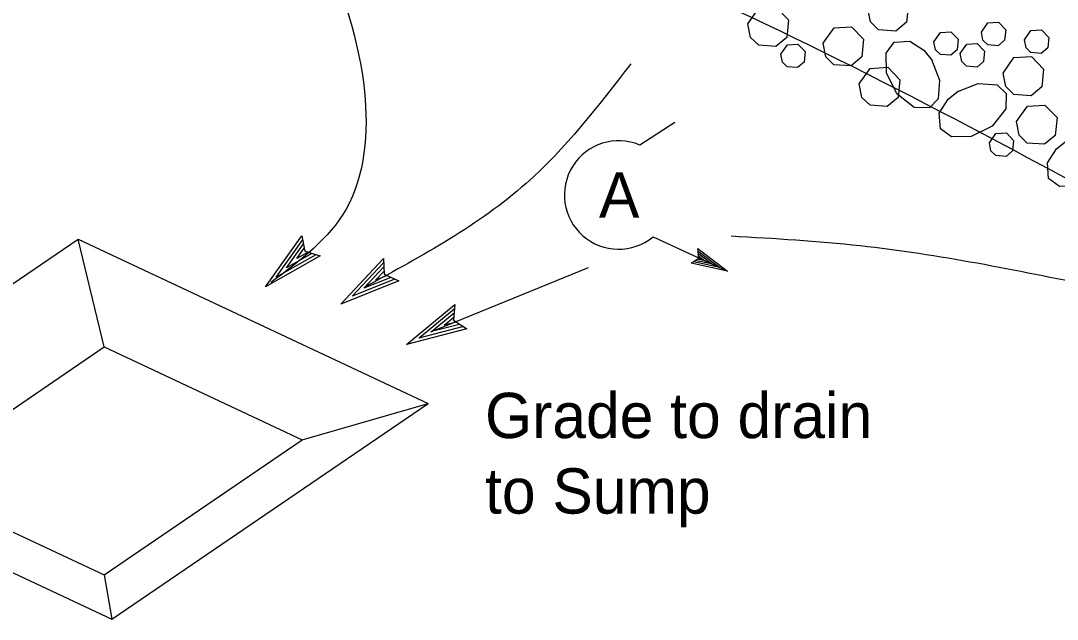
# Model space of a CAD drawing. Extents: x 6707406 to 6714471, y 1868570 to 1872341.
# Drawn here: x 6710587.1 to 6710751.9, y 1870221.6 to 1870316.7 of the extents above; entities that cross this region are included whole.
import ezdxf

# ---------------------------------------------------------------- set-up
doc = ezdxf.new("R2010")
doc.units = 0
for name, color, linetype in [('56 Stg 3 Anno', 7, 'Continuous'), ('57 Undefined', 7, 'Continuous'), ('60 Nongeo Data', 7, 'Continuous')]:
    doc.layers.add(name, color=color, linetype=linetype)

msp = doc.modelspace()

# ---------------------------------------------------------------- linework, layer by layer
at = {"layer": '56 Stg 3 Anno'}
for p, q in [((6710691.06, 1870300.55), (6710685.5, 1870296.97)), ((6710687.63, 1870282.38), (6710699.46, 1870276.93)), ((6710694.92, 1870279.02), (6710694.76, 1870280.51)), ((6710694.76, 1870280.51), (6710694.76, 1870280.51)), ((6710694.76, 1870280.51), (6710699.46, 1870276.93)), ((6710693.69, 1870278.18), (6710694.92, 1870279.02)), ((6710695.84, 1870278.6), (6710694.68, 1870278.85)), ((6710694.81, 1870280.11), (6710698.26, 1870277.49)), ((6710694.87, 1870279.71), (6710697.05, 1870278.04)), ((6710694.88, 1870279.33), (6710695.84, 1870278.6)), ((6710699.46, 1870276.93), (6710693.69, 1870278.18)), ((6710693.69, 1870278.18), (6710693.69, 1870278.18)), ((6710698.24, 1870277.49), (6710694.04, 1870278.4)), ((6710697.05, 1870278.04), (6710694.33, 1870278.63)), ((6710699.46, 1870276.93), (6710699.46, 1870276.93))]:
    msp.add_line(p, q, dxfattribs=at)
msp.add_arc((6710682.15, 1870289.04), 8.62, 67.1261, 309.4327, dxfattribs=at)
at = {"layer": '60 Nongeo Data'}
for p, q in [((6710545.91, 1870247.74), (6710596.21, 1870282.03)), ((6710596.21, 1870282.03), (6710651.87, 1870255.89)), ((6710600.37, 1870264.89), (6710596.21, 1870282.03)), ((6710626.02, 1870274.46), (6710631.78, 1870282.56)), ((6710631.78, 1870282.56), (6710631.78, 1870282.56)), ((6710631.78, 1870282.56), (6710632.26, 1870280.1)), ((6710627.69, 1870275.98), (6710631.89, 1870281.88)), ((6710629.34, 1870277.46), (6710632.05, 1870281.27)), ((6710631, 1870278.95), (6710632.16, 1870280.58)), ((6710634.68, 1870279.36), (6710626.02, 1870274.46)), ((6710634.03, 1870279.55), (6710627.68, 1870275.96)), ((6710633.36, 1870279.73), (6710629.34, 1870277.46)), ((6710632.77, 1870279.95), (6710631, 1870278.95)), ((6710632.26, 1870280.1), (6710634.68, 1870279.36)), ((6710634.68, 1870279.36), (6710634.68, 1870279.36)), ((6710637.96, 1870271.69), (6710644.74, 1870278.96)), ((6710644.74, 1870278.96), (6710644.74, 1870278.96)), ((6710644.74, 1870278.96), (6710644.89, 1870276.45)), ((6710639.81, 1870272.97), (6710644.76, 1870278.26)), ((6710641.64, 1870274.22), (6710644.84, 1870277.64)), ((6710677.28, 1870277.46), (6710652.25, 1870267.22)), ((6710647.18, 1870275.4), (6710637.96, 1870271.69)), ((6710646.57, 1870275.67), (6710639.8, 1870272.96)), ((6710645.93, 1870275.94), (6710641.64, 1870274.22)), ((6710643.49, 1870275.48), (6710644.85, 1870276.95)), ((6710645.38, 1870276.24), (6710643.49, 1870275.48)), ((6710644.89, 1870276.45), (6710647.18, 1870275.4)), ((6710647.18, 1870275.4), (6710647.18, 1870275.4)), ((6710626.02, 1870274.46), (6710626.02, 1870274.46)), ((6710637.96, 1870271.69), (6710637.96, 1870271.69)), ((6710648.41, 1870265.3), (6710656.08, 1870271.62)), ((6710650.42, 1870266.32), (6710656.01, 1870270.93)), ((6710656.08, 1870271.62), (6710655.91, 1870269.12)), ((6710656.08, 1870271.62), (6710656.08, 1870271.62)), ((6710652.4, 1870267.32), (6710656.01, 1870270.3)), ((6710654.39, 1870268.34), (6710655.93, 1870269.61)), ((6710656.36, 1870268.84), (6710654.39, 1870268.34)), ((6710655.91, 1870269.12), (6710658.04, 1870267.77)), ((6710658.04, 1870267.77), (6710648.41, 1870265.3)), ((6710657.47, 1870268.13), (6710650.4, 1870266.31)), ((6710656.87, 1870268.47), (6710652.4, 1870267.32)), ((6710658.04, 1870267.77), (6710658.04, 1870267.77)), ((6710568.89, 1870243.43), (6710600.37, 1870264.89)), ((6710600.37, 1870264.89), (6710631.82, 1870250.12)), ((6710648.41, 1870265.3), (6710648.41, 1870265.3)), ((6710601.56, 1870221.61), (6710651.87, 1870255.89)), ((6710631.82, 1870250.12), (6710651.87, 1870255.89)), ((6710600.34, 1870228.66), (6710631.82, 1870250.12)), ((6710545.91, 1870247.74), (6710601.56, 1870221.61)), ((6710568.89, 1870243.43), (6710600.34, 1870228.66)), ((6710600.34, 1870228.66), (6710601.56, 1870221.61))]:
    msp.add_line(p, q, dxfattribs=at)
for points in [[(6710721.77, 1870318.7), (6710723.51, 1870321.18), (6710726.28, 1870321.33), (6710728.21, 1870319.33), (6710727.93, 1870316.53), (6710726.22, 1870315.1), (6710723.48, 1870315.3), (6710722.19, 1870316.55), (6710721.77, 1870318.7)], [(6710702.69, 1870316.24), (6710704.43, 1870318.71), (6710707.21, 1870318.87), (6710709.14, 1870316.87), (6710708.86, 1870314.06), (6710707.15, 1870312.64), (6710704.41, 1870312.84), (6710703.11, 1870314.09), (6710702.7, 1870316.24)], [(6710714.65, 1870313.15), (6710716.39, 1870315.63), (6710719.16, 1870315.78), (6710721.09, 1870313.78), (6710720.82, 1870310.98), (6710719.1, 1870309.55), (6710716.36, 1870309.75), (6710715.07, 1870311), (6710714.65, 1870313.15)], [(6710732.27, 1870313.4), (6710733.31, 1870314.88), (6710734.98, 1870314.98), (6710736.14, 1870313.78), (6710735.97, 1870312.1), (6710734.94, 1870311.24), (6710733.3, 1870311.36), (6710732.52, 1870312.11), (6710732.27, 1870313.4)], [(6710739.81, 1870314.93), (6710740.85, 1870316.42), (6710742.52, 1870316.51), (6710743.68, 1870315.31), (6710743.51, 1870313.63), (6710742.48, 1870312.77), (6710740.83, 1870312.89), (6710740.06, 1870313.64), (6710739.81, 1870314.93)], [(6710746.66, 1870313.71), (6710747.7, 1870315.19), (6710749.37, 1870315.29), (6710750.53, 1870314.09), (6710750.36, 1870312.41), (6710749.33, 1870311.55), (6710747.69, 1870311.67), (6710746.91, 1870312.42), (6710746.66, 1870313.71)], [(6710731.89, 1870310.57), (6710733.18, 1870307.31), (6710732.92, 1870304.32), (6710731.57, 1870302.9), (6710729.15, 1870302.95), (6710726.39, 1870305.1), (6710724.73, 1870308.44), (6710724.67, 1870311.58), (6710725.93, 1870313.35), (6710728.43, 1870313.51), (6710730.66, 1870312.08), (6710731.98, 1870310.44)], [(6710707.92, 1870311.44), (6710708.97, 1870312.92), (6710710.63, 1870313.02), (6710711.79, 1870311.82), (6710711.63, 1870310.13), (6710710.6, 1870309.28), (6710708.95, 1870309.4), (6710708.18, 1870310.15), (6710707.93, 1870311.44)], [(6710736.45, 1870311.54), (6710737.49, 1870313.03), (6710739.16, 1870313.12), (6710740.32, 1870311.92), (6710740.15, 1870310.24), (6710739.12, 1870309.38), (6710737.47, 1870309.5), (6710736.7, 1870310.25), (6710736.45, 1870311.54)], [(6710743.26, 1870308.41), (6710745, 1870310.88), (6710747.78, 1870311.04), (6710749.71, 1870309.04), (6710749.43, 1870306.23), (6710747.71, 1870304.81), (6710744.97, 1870305.01), (6710743.68, 1870306.26), (6710743.26, 1870308.41)], [(6710720.4, 1870306.7), (6710722.14, 1870309.17), (6710724.92, 1870309.33), (6710726.85, 1870307.33), (6710726.57, 1870304.53), (6710724.85, 1870303.1), (6710722.11, 1870303.3), (6710720.82, 1870304.55), (6710720.4, 1870306.7)], [(6710736.07, 1870305.49), (6710739.32, 1870306.78), (6710742.31, 1870306.53), (6710743.73, 1870305.18), (6710743.69, 1870302.75), (6710741.53, 1870299.99), (6710738.2, 1870298.33), (6710735.06, 1870298.27), (6710733.29, 1870299.53), (6710733.13, 1870302.03), (6710734.56, 1870304.27), (6710736.2, 1870305.58)], [(6710745.4, 1870300.7), (6710747.14, 1870303.17), (6710749.92, 1870303.33), (6710751.85, 1870301.33), (6710751.57, 1870298.52), (6710749.85, 1870297.1), (6710747.11, 1870297.3), (6710745.82, 1870298.55), (6710745.4, 1870300.7)], [(6710741.08, 1870297.34), (6710742.12, 1870298.83), (6710743.79, 1870298.92), (6710744.94, 1870297.72), (6710744.78, 1870296.04), (6710743.75, 1870295.18), (6710742.1, 1870295.3), (6710741.33, 1870296.05), (6710741.08, 1870297.34)], [(6710753.27, 1870297.62), (6710756.53, 1870298.91), (6710759.51, 1870298.65), (6710760.94, 1870297.3), (6710760.89, 1870294.88), (6710758.73, 1870292.12), (6710755.4, 1870290.46), (6710752.26, 1870290.4), (6710750.49, 1870291.66), (6710750.33, 1870294.16), (6710751.76, 1870296.4), (6710753.4, 1870297.71)]]:
    msp.add_lwpolyline(points, dxfattribs=at)
for points in [[(6710505.99, 1870337.51), (6710532.99, 1870347.83), (6710590.83, 1870352.57), (6710625.79, 1870346.13), (6710776.97, 1870278.77)], [(6710635.61, 1870328.27), (6710641.74, 1870305.49), (6710638.82, 1870286.79), (6710626.85, 1870275.11)], [(6710684.07, 1870309.87), (6710667.43, 1870290.88), (6710642.03, 1870274.53)], [(6710757.64, 1870274.53), (6710720.56, 1870280.95), (6710700.05, 1870282.48)]]:
    msp.add_spline(points, degree=3, dxfattribs=at)

# ---------------------------------------------------------------- texts
at = {"layer": '57 Undefined'}
for s, height, p in [('A', 7.21, (6710679.02, 1870285.43)), ('Grade to drain', 7.2002, (6710660.91, 1870250.4)), ('to Sump', 7.2, (6710660.91, 1870238.4))]:
    msp.add_text(s, height=height, dxfattribs=at).set_placement(p)

doc.saveas('drawing.dxf')
